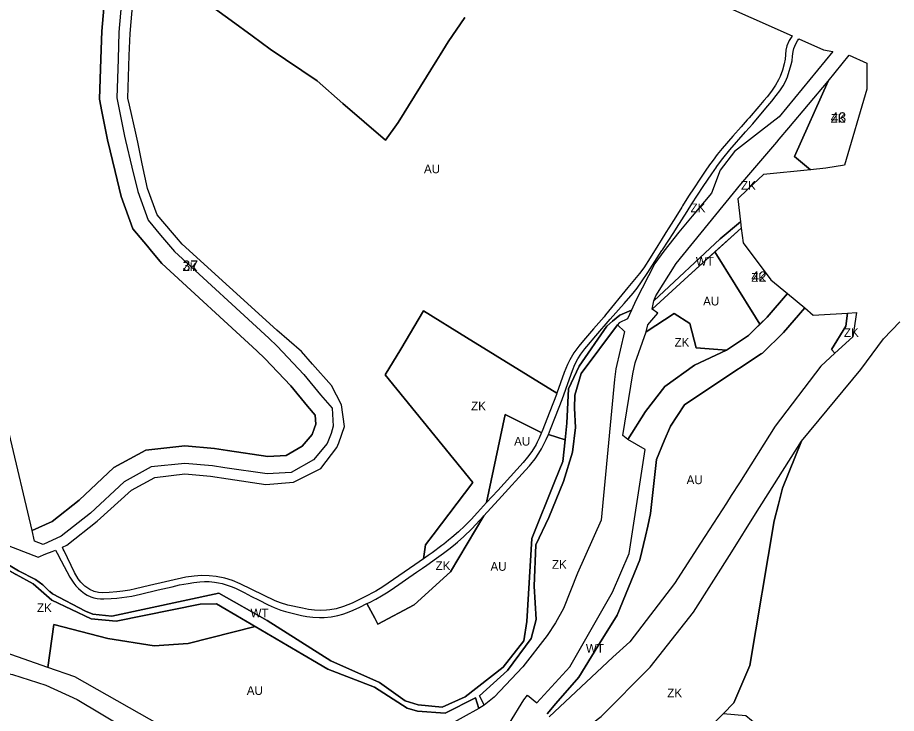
# Model space of a CAD drawing. Extents: x -521261 to -517465, y -1182764 to -1179456.
# Drawn here: x -518710 to -518203, y -1181825 to -1181423 of the extents above; entities that cross this region are included whole.
import ezdxf

# ---------------------------------------------------------------- set-up
doc = ezdxf.new("R2010")
doc.units = 0
for name, color, linetype in [('90640013', 7, 'Continuous'), ('90710013', 7, 'Continuous'), ('90710023', 7, 'Continuous'), ('90750013', 7, 'Continuous'), ('ID_navrh', 7, 'Continuous')]:
    doc.layers.add(name, color=color, linetype=linetype)

msp = doc.modelspace()

# ---------------------------------------------------------------- linework, layer by layer
at = {"layer": '90640013'}
msp.add_lwpolyline([(-518304.74, -1181550.83), (-518292.99, -1181541.03), (-518292.56, -1181544.69), (-518323.21, -1181572.31), (-518343.97, -1181591.39), (-518343, -1181586.61)], close=True, dxfattribs=at)
for points in [[(-518426.44, -1181830.61), (-518418.2, -1181817.08), (-518415.97, -1181814.43), (-518410.71, -1181818.75), (-518391.63, -1181798.11), (-518366.86, -1181754.89), (-518357.33, -1181732.66), (-518348.13, -1181672.51), (-518358.17, -1181666.8), (-518347.92, -1181650.56), (-518336.69, -1181636.07), (-518319.67, -1181623.86), (-518301.2, -1181615.05), (-518288.4, -1181606.62), (-518277.63, -1181596.13), (-518265.919, -1181582.387), (-518255.964, -1181590.678), (-518268.16, -1181604.99), (-518280.245, -1181616.761), (-518281.034, -1181617.28), (-518306.77, -1181634.23), (-518325.31, -1181646.7), (-518333.51, -1181659), (-518337.01, -1181667.42), (-518341.51, -1181678.22), (-518345, -1181709.41), (-518346.59, -1181716.86), (-518347.8, -1181722.52), (-518351.11, -1181736.23), (-518364.24, -1181768.26), (-518375.39, -1181786.06), (-518386.42, -1181804.08), (-518399.59, -1181819.23), (-518404.75, -1181825.16)], [(-518745.97, -1181721.22), (-518709.95, -1181742.54), (-518700.11, -1181747.5), (-518695.82, -1181750.75), (-518692.16, -1181754.25), (-518691.89, -1181754.49), (-518690.34, -1181755.87), (-518671.23, -1181765.79), (-518666.97, -1181767.61), (-518656.07, -1181768.76), (-518594.21, -1181755.48), (-518566.25, -1181771.18), (-518529.59, -1181794.49), (-518501.45, -1181807.02), (-518486.56, -1181817.64), (-518479.21, -1181819.93), (-518465.35, -1181821.3), (-518451.98, -1181815.29), (-518430.01, -1181798.28), (-518418.1, -1181782.97), (-518416.35, -1181771.83), (-518413.6, -1181723.96), (-518400.32, -1181690.69), (-518395.65, -1181679.45), (-518394.18, -1181666.81), (-518393.34, -1181657.24), (-518392.34, -1181637.45), (-518386.22, -1181624.34), (-518370.22, -1181601.17), (-518366.91, -1181598.39), (-518362.67, -1181594.83), (-518355.96, -1181592.03), (-518358.22, -1181597.08), (-518363.05, -1181599.36), (-518364.04, -1181600.44), (-518385.08, -1181628.59), (-518388.69, -1181641.14), (-518388.81, -1181648.68), (-518388.2, -1181659.86), (-518390.12, -1181674.09), (-518395.27, -1181691.01), (-518403.75, -1181711.81), (-518411.22, -1181727.56), (-518412.23, -1181751.5), (-518410.94, -1181770.72), (-518413.83, -1181781.65), (-518427.58, -1181800.22), (-518443.71, -1181814.88), (-518441.04, -1181820.23), (-518444.06, -1181822.06), (-518446.06, -1181816.02), (-518463.58, -1181824.77), (-518479.61, -1181823.57), (-518485.49, -1181821.82), (-518504.33, -1181809.73), (-518531.34, -1181799.45), (-518595.57, -1181761.58), (-518605.06, -1181761.8), (-518653.59, -1181771.67), (-518667.99, -1181770.25), (-518690.65, -1181759.52), (-518701.51, -1181750.01), (-518711.17, -1181744.79)]]:
    msp.add_lwpolyline(points, dxfattribs=at)
at = {"layer": '90710013'}
msp.add_lwpolyline([(-518452.27, -1181422.89), (-518461.77, -1181436.96), (-518466.48, -1181444.53), (-518468.37, -1181447.52), (-518490.77, -1181483.59), (-518497.921, -1181493.847), (-518522.59, -1181472.57), (-518537.45, -1181459.55), (-518564.54, -1181441.21), (-518575, -1181433.44), (-518587.17, -1181424.75), (-518599.62, -1181415.62)], dxfattribs=at)
for points in [[(-518245.14, -1181441.64), (-518239.78, -1181442.56), (-518270.78, -1181480.36), (-518280.81, -1181488.17), (-518296.43, -1181500.33), (-518304.73, -1181511.04), (-518309.8, -1181524.46), (-518320.86, -1181537.69), (-518328.61, -1181546.95), (-518337.29, -1181557.9), (-518342.54, -1181565.05), (-518353.55, -1181586.4), (-518355.96, -1181592.03), (-518362.67, -1181594.83), (-518366.91, -1181598.39), (-518370.22, -1181601.17), (-518386.22, -1181624.34), (-518392.34, -1181637.45), (-518393.34, -1181657.24), (-518394.18, -1181666.81), (-518403.95, -1181663.79), (-518402.66, -1181660.73), (-518399.81, -1181653.43), (-518396.07, -1181643.56), (-518391.82, -1181631.62), (-518390.11, -1181626.85), (-518388.64, -1181623.36), (-518386.98, -1181620.16), (-518385.28, -1181617.37), (-518382.91, -1181614.3), (-518381.83, -1181613.01), (-518376.62, -1181606.83), (-518368.36, -1181597.27), (-518368.24, -1181597.13), (-518360.25, -1181588.07), (-518355.05, -1181582.12), (-518352.7, -1181579.27), (-518350.1, -1181575.69), (-518346.55, -1181570.23), (-518338.36, -1181557.58), (-518338.07, -1181557.14), (-518331.57, -1181547.04), (-518329.99, -1181544.57), (-518323.88, -1181535.05), (-518321.03, -1181530.6), (-518314.57, -1181520.61), (-518309.67, -1181513.28), (-518306.93, -1181509.41), (-518306.81, -1181509.23), (-518303.15, -1181504.38), (-518299.1, -1181499.41), (-518290.21, -1181488.97), (-518285.98, -1181484.33), (-518278.42, -1181475.23), (-518274.99, -1181471.21), (-518272.42, -1181467.98), (-518270.4, -1181465.23), (-518268.39, -1181462.35), (-518267.01, -1181459.93), (-518265.9, -1181457.23), (-518263.73, -1181450.15), (-518263.28, -1181447.91), (-518262.97, -1181445.29), (-518262.57, -1181442.56), (-518262.19, -1181440.84), (-518261.09, -1181438.11), (-518260.11, -1181436.42), (-518259.28, -1181435.3)], [(-518270.6, -1181493.25), (-518265.05, -1181486.75), (-518242.44, -1181459.71), (-518261.84, -1181503.31), (-518252.51, -1181510.92), (-518279.66, -1181513.62), (-518288.8, -1181522.19), (-518294.6, -1181527.65), (-518292.99, -1181541.03), (-518304.74, -1181550.83), (-518343, -1181586.61), (-518341.85, -1181583.76), (-518330.14, -1181565.02), (-518292.92, -1181519.25), (-518272.08, -1181494.96)], [(-518473.41, -1181733.78), (-518476, -1181735.601), (-518474.928, -1181727.654), (-518470.508, -1181721.831), (-518447.55, -1181691.59), (-518498.1, -1181629.37), (-518489.237, -1181614.442), (-518476.15, -1181592.4), (-518451.208, -1181607.763), (-518399.035, -1181639.9), (-518399.35, -1181640.79), (-518403.02, -1181650.57), (-518407.53, -1181661.9), (-518407.83, -1181662.59), (-518408.48, -1181662.39), (-518428.88, -1181652.36), (-518439.635, -1181703.129), (-518444.89, -1181708.88), (-518448.47, -1181712.84), (-518452.15, -1181716.64), (-518455.79, -1181720.01), (-518459.63, -1181723.36), (-518461.56, -1181724.91), (-518464.37, -1181727.16), (-518465.48, -1181727.97), (-518471.13, -1181732.11)], [(-518355.26, -1181628.81), (-518353.86, -1181622.4), (-518347.44, -1181604.6), (-518331.35, -1181594), (-518322.27, -1181599.7), (-518318.67, -1181613.69), (-518301.2, -1181615.05), (-518319.67, -1181623.86), (-518336.69, -1181636.07), (-518347.92, -1181650.56), (-518358.17, -1181666.8), (-518361, -1181664.46)], [(-518240.53, -1181614.63), (-518232.17, -1181601.16), (-518231.23, -1181593.65), (-518226.03, -1181593.35), (-518228.23, -1181607.32), (-518238.63, -1181616.76)], [(-518364.91, -1181625.87), (-518365.73, -1181632.04), (-518373.41, -1181713.36), (-518387.15, -1181743.87), (-518395.15, -1181764.35), (-518399.93, -1181772.58), (-518404.68, -1181779.92), (-518418.7, -1181798.11), (-518435.27, -1181815.58), (-518441.04, -1181820.23), (-518443.71, -1181814.88), (-518427.58, -1181800.22), (-518413.83, -1181781.65), (-518410.94, -1181770.72), (-518412.23, -1181751.5), (-518411.22, -1181727.56), (-518403.75, -1181711.81), (-518395.27, -1181691.01), (-518390.12, -1181674.09), (-518388.2, -1181659.86), (-518388.81, -1181648.68), (-518388.69, -1181641.14), (-518385.08, -1181628.59), (-518364.04, -1181600.44), (-518360.05, -1181604.26)], [(-518302.96, -1181825.14), (-518312.78, -1181834.79), (-518347.83, -1181851.39), (-518354.74, -1181851.96), (-518373.71, -1181854.29), (-518379.46, -1181853.84), (-518396.5, -1181852.96), (-518412.79, -1181856.47), (-518392.04, -1181840.87), (-518373.39, -1181826.78), (-518345.1, -1181798.17), (-518320.12, -1181766.51), (-518297.97, -1181731.65), (-518284.29, -1181709.64), (-518257.78, -1181667.72), (-518268.81, -1181694.86), (-518271.03, -1181704.12), (-518273.51, -1181713.67), (-518287.7, -1181797.29), (-518296.94, -1181818.88)], [(-518448.24, -1181718.36), (-518441.26, -1181710.8), (-518460.42, -1181743.1), (-518481.38, -1181762.2), (-518502.35, -1181773.42), (-518504.203, -1181769.952), (-518508.692, -1181761.546), (-518507.21, -1181760.8), (-518503.53, -1181758.88), (-518500.36, -1181757.09), (-518497.49, -1181755.36), (-518494.82, -1181753.53), (-518480.13, -1181743.37), (-518476.726, -1181740.98), (-518474.22, -1181739.22), (-518468.5, -1181735.18), (-518465.88, -1181733.33), (-518464.59, -1181732.37), (-518461.48, -1181730.07), (-518458.77, -1181727.94), (-518456.47, -1181725.99), (-518452.81, -1181722.77)], [(-518595.57, -1181761.58), (-518573.313, -1181774.703), (-518611.95, -1181784.61), (-518631.48, -1181785.91), (-518658.29, -1181781.74), (-518689.53, -1181773.67), (-518693.056, -1181798.326), (-518717.64, -1181789.82), (-518728.706, -1181734.492), (-518711.17, -1181744.79), (-518701.51, -1181750.01), (-518690.65, -1181759.52), (-518667.99, -1181770.25), (-518653.59, -1181771.67), (-518605.06, -1181761.8)]]:
    msp.add_lwpolyline(points, close=True, dxfattribs=at)
at = {"layer": '90710023'}
msp.add_lwpolyline([(-518649.97, -1181409.3), (-518651.9, -1181431.4), (-518652.41, -1181447.08), (-518653.14, -1181469.35), (-518651.95, -1181475.2), (-518648.66, -1181491.51), (-518648.14, -1181494.08), (-518644.42, -1181509.49), (-518641.06, -1181523.42), (-518635.13, -1181539.99), (-518627.86, -1181548.63), (-518625.52, -1181551.41), (-518619.87, -1181558.14), (-518565.45, -1181608.23), (-518560.62, -1181612.85), (-518545.13, -1181629.18), (-518535.47, -1181640.99), (-518528.86, -1181648.59), (-518528.2, -1181658.97), (-518529.46, -1181663.17), (-518531.67, -1181669.01), (-518539.52, -1181678.39), (-518552.39, -1181685.71), (-518566.42, -1181686.57), (-518590.8, -1181683.04), (-518597.91, -1181681.89), (-518613.8, -1181680.5), (-518633.31, -1181682.58), (-518648.88, -1181691.12), (-518668.32, -1181709.36), (-518685.24, -1181722.6), (-518695.67, -1181727.41), (-518700.64, -1181725.43), (-518702.073, -1181719.351), (-518690.485, -1181714.007), (-518674.836, -1181701.761), (-518654.799, -1181682.961), (-518636.362, -1181672.849), (-518613.895, -1181670.453), (-518596.674, -1181671.96), (-518589.285, -1181673.155), (-518566.005, -1181676.526), (-518555.317, -1181675.871), (-518546.031, -1181670.589), (-518540.424, -1181663.889), (-518538.937, -1181659.96), (-518538.294, -1181657.815), (-518538.625, -1181652.6), (-518543.115, -1181647.438), (-518552.638, -1181635.796), (-518567.708, -1181619.908), (-518572.293, -1181615.523), (-518627.115, -1181565.062), (-518633.175, -1181557.845), (-518635.511, -1181555.069), (-518643.939, -1181545.052), (-518650.656, -1181526.285), (-518654.147, -1181511.81), (-518658.43, -1181493.647), (-518661.751, -1181477.185), (-518663.173, -1181470.194), (-518662.405, -1181446.754), (-518661.886, -1181430.802), (-518659.932, -1181408.429)], dxfattribs=at)
for points in [[(-518252.51, -1181510.92), (-518261.84, -1181503.31), (-518242.44, -1181459.71), (-518230.37, -1181444.73), (-518220.1, -1181449.28), (-518219.98, -1181464.38), (-518232.93, -1181508.15), (-518243.76, -1181510.04)], [(-518284.276, -1181596.115), (-518307.76, -1181558.387), (-518292.56, -1181544.69), (-518291.45, -1181553.08), (-518275.51, -1181574.4), (-518265.919, -1181582.387), (-518277.63, -1181596.13), (-518281.762, -1181600.154)]]:
    msp.add_lwpolyline(points, close=True, dxfattribs=at)
at = {"layer": '90750013'}
for points in [[(-518310.97, -1181412.15), (-518263.14, -1181433.58), (-518263.41, -1181433.91), (-518264.9, -1181436.3), (-518266.24, -1181439.37), (-518266.86, -1181441.84), (-518267.3, -1181446.97), (-518267.78, -1181449.62), (-518268.86, -1181453.31), (-518270.19, -1181457.1), (-518271.06, -1181459.03), (-518272.77, -1181461.98), (-518275.15, -1181465.46), (-518277.7, -1181468.77), (-518279.52, -1181470.96), (-518282.53, -1181474.44), (-518288.05, -1181480.82), (-518289.09, -1181482.01), (-518292.71, -1181486.16), (-518297.47, -1181491.58), (-518303.64, -1181498.62), (-518306.46, -1181502.09), (-518308.9, -1181505.26), (-518310.17, -1181506.99), (-518311.01, -1181508.14), (-518313.46, -1181511.68), (-518316.56, -1181516.26), (-518319.86, -1181521.29), (-518322.98, -1181526.21), (-518326.45, -1181531.75), (-518326.88, -1181532.43), (-518330.44, -1181538.14), (-518334.33, -1181544.36), (-518336.05, -1181547.15), (-518338.83, -1181551.64), (-518340.67, -1181554.63), (-518345.13, -1181561.85), (-518348.85, -1181567.48), (-518351.43, -1181570.85), (-518358.03, -1181578.9), (-518370.88, -1181594.65), (-518371.79, -1181595.78), (-518377.91, -1181602.87), (-518383.59, -1181609.43), (-518386.34, -1181612.73), (-518389.22, -1181616.62), (-518391.62, -1181620.62), (-518392.94, -1181623.31), (-518394.86, -1181628.09), (-518399.035, -1181639.9), (-518451.208, -1181607.763), (-518476.15, -1181592.4), (-518489.237, -1181614.442), (-518498.1, -1181629.37), (-518447.55, -1181691.59), (-518470.508, -1181721.831), (-518474.928, -1181727.654), (-518476, -1181735.601), (-518481.12, -1181739.2), (-518499.45, -1181751.79), (-518503.58, -1181754.3), (-518510.3, -1181757.87), (-518517.21, -1181761.21), (-518522.29, -1181763.25), (-518526.41, -1181764.45), (-518530.11, -1181765.16), (-518532.07, -1181765.39), (-518535.33, -1181765.5), (-518538.93, -1181765.3), (-518542.47, -1181764.83), (-518545.96, -1181764.18), (-518554.41, -1181762.35), (-518558.66, -1181761.1), (-518561.72, -1181759.85), (-518581.85, -1181750.04), (-518586.4, -1181748.21), (-518590.77, -1181746.82), (-518595.7, -1181745.83), (-518599.81, -1181745.39), (-518604.18, -1181745.33), (-518608.39, -1181745.59), (-518613.2, -1181746.27), (-518634.23, -1181751.13), (-518642.41, -1181753.05), (-518645.56, -1181753.69), (-518649.72, -1181754.37), (-518653.21, -1181754.77), (-518657.6, -1181755.13), (-518661.18, -1181755.29), (-518663.71, -1181755.13), (-518666.14, -1181754.54), (-518668.74, -1181753.42), (-518671.67, -1181751.44), (-518674, -1181749.13), (-518675.49, -1181747.24), (-518677.55, -1181743.5), (-518683.53, -1181731.12), (-518684.03, -1181730.1), (-518684.6, -1181728.92), (-518681.93, -1181727.79), (-518664.53, -1181713.89), (-518644.73, -1181696.07), (-518631.16, -1181688.65), (-518613.95, -1181686.61), (-518599.11, -1181687.82), (-518588.94, -1181689.49), (-518567.08, -1181692.76), (-518551.05, -1181691.45), (-518535.34, -1181683.41), (-518526.17, -1181671.36), (-518525.01, -1181668.56), (-518521.74, -1181659.28), (-518523.32, -1181646.7), (-518529.15, -1181635.61), (-518540.13, -1181623.13), (-518546.52, -1181615.85), (-518560.78, -1181603.65), (-518615.36, -1181553.87), (-518618.68, -1181550.02), (-518621, -1181547.31), (-518629.92, -1181536.95), (-518635.46, -1181521.68), (-518638.43, -1181507.51), (-518641.06, -1181494.99), (-518642.25, -1181489.66), (-518645.87, -1181473.52), (-518646.77, -1181469.51), (-518645.93, -1181444.88), (-518645.49, -1181432.17), (-518642.96, -1181402.9)], [(-518659.932, -1181408.429), (-518661.886, -1181430.802), (-518662.405, -1181446.754), (-518663.173, -1181470.194), (-518661.751, -1181477.185), (-518658.43, -1181493.647), (-518654.147, -1181511.81), (-518650.656, -1181526.285), (-518643.939, -1181545.052), (-518635.511, -1181555.069), (-518633.175, -1181557.845), (-518627.115, -1181565.062), (-518572.293, -1181615.523), (-518567.708, -1181619.908), (-518552.638, -1181635.796), (-518543.115, -1181647.438), (-518538.625, -1181652.6), (-518538.294, -1181657.815), (-518538.937, -1181659.96), (-518540.424, -1181663.889), (-518546.031, -1181670.589), (-518555.317, -1181675.871), (-518566.005, -1181676.526), (-518589.285, -1181673.155), (-518596.674, -1181671.96), (-518613.895, -1181670.453), (-518636.362, -1181672.849), (-518654.799, -1181682.961), (-518674.836, -1181701.761), (-518690.485, -1181714.007), (-518702.073, -1181719.351), (-518715.36, -1181662.99)], [(-518599.62, -1181415.62), (-518587.17, -1181424.75), (-518575, -1181433.44), (-518564.54, -1181441.21), (-518537.45, -1181459.55), (-518522.59, -1181472.57), (-518497.921, -1181493.847), (-518490.77, -1181483.59), (-518468.37, -1181447.52), (-518466.48, -1181444.53), (-518461.77, -1181436.96), (-518452.27, -1181422.89)], [(-518404.75, -1181825.16), (-518399.59, -1181819.23), (-518386.42, -1181804.08), (-518375.39, -1181786.06), (-518364.24, -1181768.26), (-518351.11, -1181736.23), (-518347.8, -1181722.52), (-518346.59, -1181716.86), (-518345, -1181709.41), (-518341.51, -1181678.22), (-518337.01, -1181667.42), (-518333.51, -1181659), (-518325.31, -1181646.7), (-518306.77, -1181634.23), (-518281.034, -1181617.28), (-518280.245, -1181616.761), (-518268.16, -1181604.99), (-518255.964, -1181590.678), (-518250.99, -1181594.82), (-518241.23, -1181594.25), (-518237.69, -1181594.04), (-518231.23, -1181593.65), (-518232.17, -1181601.16), (-518240.53, -1181614.63), (-518238.63, -1181616.76), (-518246.56, -1181624.36), (-518272.91, -1181659.04), (-518293.66, -1181691.71), (-518298.38, -1181699.15), (-518301.03, -1181703.4), (-518316.1, -1181726.67), (-518331.13, -1181749.88), (-518356.9, -1181783.65), (-518366.69, -1181792.51), (-518397.42, -1181821.23), (-518403.42, -1181826.84)], [(-518196.73, -1181867.61), (-518217.29, -1181863.99), (-518237.7, -1181854.2), (-518243.96, -1181856.31), (-518273.09, -1181840.42), (-518283.47, -1181831.75), (-518289.97, -1181826.31), (-518302.96, -1181825.14), (-518296.94, -1181818.88), (-518287.7, -1181797.29), (-518273.51, -1181713.67), (-518271.03, -1181704.12), (-518268.81, -1181694.86), (-518257.78, -1181667.72), (-518223.62, -1181626.24), (-518210.43, -1181608.65), (-518201.08, -1181598.66)], [(-518725.19, -1181724.49), (-518698.65, -1181734.68), (-518694.04, -1181732.84), (-518690.49, -1181731.42), (-518688.52, -1181730.58), (-518687.57, -1181732.35), (-518685.19, -1181736.84), (-518680.2, -1181746.19), (-518679.15, -1181748.02), (-518678.03, -1181749.68), (-518676.82, -1181751.19), (-518675.25, -1181752.79), (-518673.76, -1181754.16), (-518671.84, -1181755.58), (-518670.22, -1181756.56), (-518668.24, -1181757.51), (-518666.38, -1181758.15), (-518664.49, -1181758.57), (-518662.65, -1181758.77), (-518660.63, -1181758.78), (-518656.39, -1181758.59), (-518653.09, -1181758.35), (-518647.36, -1181757.65), (-518644.43, -1181757.14), (-518639.38, -1181755.99), (-518629.3, -1181753.61), (-518621.19, -1181751.73), (-518616.93, -1181750.71), (-518612, -1181749.82), (-518608.73, -1181749.39), (-518605.28, -1181748.9), (-518602.6, -1181748.69), (-518599.82, -1181748.83), (-518596.79, -1181749.2), (-518594.43, -1181749.5), (-518592.28, -1181749.95), (-518589.35, -1181750.8), (-518587.06, -1181751.65), (-518584.68, -1181752.68), (-518579.69, -1181755.1), (-518575.34, -1181757.32), (-518571.29, -1181759.37), (-518565.71, -1181762.16), (-518562.2, -1181763.84), (-518558.38, -1181765.25), (-518555.68, -1181766.05), (-518551.2, -1181767.19), (-518546.52, -1181768.29), (-518543.34, -1181768.89), (-518540.03, -1181769.35), (-518536.18, -1181769.61), (-518533.43, -1181769.58), (-518529.36, -1181769.15), (-518525.6, -1181768.37), (-518522.73, -1181767.57), (-518519.94, -1181766.66), (-518516.74, -1181765.39), (-518512.83, -1181763.63), (-518508.692, -1181761.546), (-518504.203, -1181769.952), (-518502.35, -1181773.42), (-518481.38, -1181762.2), (-518460.42, -1181743.1), (-518441.26, -1181710.8), (-518430.81, -1181699.37), (-518417.17, -1181684.34), (-518414.95, -1181681.93), (-518414.04, -1181680.93), (-518411.64, -1181677.96), (-518409.37, -1181674.6), (-518407.95, -1181672.17), (-518406.68, -1181669.78), (-518405.17, -1181666.68), (-518403.95, -1181663.79), (-518394.18, -1181666.81), (-518395.65, -1181679.45), (-518400.32, -1181690.69), (-518413.6, -1181723.96), (-518416.35, -1181771.83), (-518418.1, -1181782.97), (-518430.01, -1181798.28), (-518451.98, -1181815.29), (-518465.35, -1181821.3), (-518479.21, -1181819.93), (-518486.56, -1181817.64), (-518501.45, -1181807.02), (-518529.59, -1181794.49), (-518566.25, -1181771.18), (-518594.21, -1181755.48), (-518656.07, -1181768.76), (-518666.97, -1181767.61), (-518671.23, -1181765.79), (-518690.34, -1181755.87), (-518691.89, -1181754.49), (-518692.16, -1181754.25), (-518695.82, -1181750.75), (-518700.11, -1181747.5), (-518709.95, -1181742.54), (-518745.97, -1181721.22)]]:
    msp.add_lwpolyline(points, dxfattribs=at)
for points in [[(-518281.762, -1181600.154), (-518288.4, -1181606.62), (-518301.2, -1181615.05), (-518318.67, -1181613.69), (-518322.27, -1181599.7), (-518331.35, -1181594), (-518347.44, -1181604.6), (-518346.6, -1181600.52), (-518340.75, -1181593.69), (-518343.97, -1181591.39), (-518323.21, -1181572.31), (-518307.76, -1181558.387), (-518284.276, -1181596.115)], [(-518408.48, -1181662.39), (-518407.83, -1181662.59), (-518409.26, -1181665.86), (-518410.41, -1181668.2), (-518411.08, -1181669.58), (-518413.54, -1181673.62), (-518416, -1181676.99), (-518418.57, -1181679.95), (-518433.23, -1181696.12), (-518439.635, -1181703.129), (-518428.88, -1181652.36)], [(-518621.41, -1181835.63), (-518677.32, -1181803.77), (-518693.056, -1181798.326), (-518689.53, -1181773.67), (-518658.29, -1181781.74), (-518631.48, -1181785.91), (-518611.95, -1181784.61), (-518573.313, -1181774.703), (-518573.313, -1181774.703), (-518531.34, -1181799.45), (-518504.33, -1181809.73), (-518485.49, -1181821.82), (-518479.61, -1181823.57), (-518463.58, -1181824.77), (-518446.06, -1181816.02), (-518444.06, -1181822.06), (-518462.21, -1181832.05), (-518491.58, -1181846.12), (-518525.9, -1181851.87), (-518558.11, -1181854.84), (-518578.55, -1181850.79), (-518602.16, -1181844.15)], [(-518620.85, -1181848.06), (-518597.74, -1181856.58), (-518627.84, -1181863.67), (-518653.23, -1181864.79), (-518673.3, -1181859.85), (-518689.43, -1181847.62), (-518708.84, -1181840.52), (-518783.87, -1181833.43), (-518802.16, -1181829.32), (-518822.01, -1181813.66), (-518823.91, -1181809.28), (-518803.25, -1181801.73), (-518772.27, -1181796.81), (-518760.7, -1181796.26), (-518739.83, -1181797.72), (-518713.38, -1181802.54), (-518694.2, -1181808.7), (-518676.08, -1181816.9), (-518635.51, -1181841.21)]]:
    msp.add_lwpolyline(points, close=True, dxfattribs=at)

# ---------------------------------------------------------------- texts
at = {"layer": '90640013'}
for rotation, p in [(0, (-518318.813, -1181566.21)), (360, (-518575.955, -1181769.438)), (0, (-518382.299, -1181789.842))]:
    msp.add_text('WT', height=5, rotation=rotation, dxfattribs=at).set_placement(p)
at = {"layer": '90710013'}
for rotation, p in [(360, (-518292.72, -1181522.449)), (0, (-518321.865, -1181535.397)), (360, (-518233.28, -1181607.426)), (0, (-518331.1, -1181613.108)), (0, (-518448.567, -1181649.864)), (0, (-518469.084, -1181742.11)), (0, (-518401.88, -1181741.408)), (0, (-518699.212, -1181766.409)), (0, (-518335.285, -1181815.589))]:
    msp.add_text('ZK', height=5, rotation=rotation, dxfattribs=at).set_placement(p)
at = {"layer": '90710023'}
for rotation, p in [(360, (-518240.91, -1181483.677)), (0, (-518615.137, -1181569.292)), (0, (-518286.84, -1181575.622))]:
    msp.add_text('ZK', height=5, rotation=rotation, dxfattribs=at).set_placement(p)
at = {"layer": '90750013'}
for rotation, p in [(0, (-518475.793, -1181512.9)), (0, (-518314.601, -1181589.279)), (0, (-518423.733, -1181670.268)), (360, (-518324.14, -1181692.499)), (360, (-518437.379, -1181742.545)), (0, (-518578.099, -1181814.255))]:
    msp.add_text('AU', height=5, rotation=rotation, dxfattribs=at).set_placement(p)
at = {"layer": 'ID_navrh'}
for s, p in [('43', (-518240.91, -1181483.677)), ('37', (-518615.137, -1181569.292)), ('42', (-518286.84, -1181575.622))]:
    msp.add_text(s, height=6, rotation=0, dxfattribs=at).set_placement(p)

doc.saveas('drawing.dxf')
